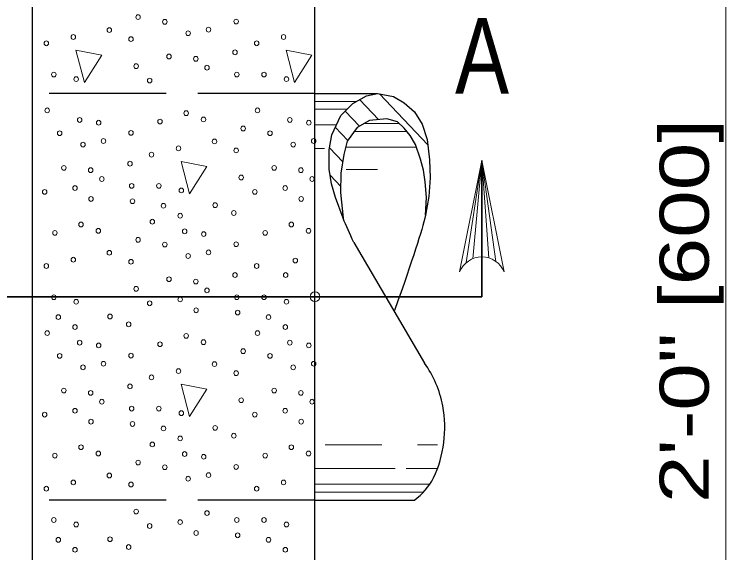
# Model space of a CAD drawing. Extents: x -410.5 to -376.5, y 1617.6 to 1661.6.
# Drawn here: x -401.689 to -399.43, y 1623.076 to 1624.784 of the extents above; entities that cross this region are included whole.
import ezdxf
from ezdxf.enums import TextEntityAlignment as Align

# ---------------------------------------------------------------- set-up
doc = ezdxf.new("R2010")
doc.units = 0
doc.header["$LTSCALE"] = 0.062
doc.header["$PDMODE"] = 32
doc.header["$PDSIZE"] = 0.031
doc.linetypes.add('LONG_DASHED', pattern=[7.5, 6, -1.5])
doc.layers.add('1', color=7, linetype='Continuous', lineweight=13)

msp = doc.modelspace()

# ---------------------------------------------------------------- linework, layer by layer
at = {"layer": '1'}
for p, q in [((-399.42975, 1626.3615), (-399.42975, 1621.41433)), ((-400.82575, 1624.67075), (-400.79875, 1624.56825)), ((-400.529, 1624.53167), (-400.376, 1624.36975)), ((-400.73433, 1624.508), (-400.60125, 1624.508)), ((-400.59167, 1624.51333), (-400.53217, 1624.45025)), ((-400.73433, 1624.483), (-400.63208, 1624.483)), ((-400.63783, 1624.47725), (-400.59275, 1624.4295)), ((-400.73433, 1624.433), (-400.66625, 1624.433)), ((-400.57825, 1624.43783), (-400.46692, 1624.43783)), ((-400.6695, 1624.426), (-400.62967, 1624.38392)), ((-400.60917, 1624.41283), (-400.4425, 1624.41283)), ((-400.63642, 1624.36292), (-400.412, 1624.36292)), ((-400.73433, 1624.35808), (-400.704, 1624.35808)), ((-400.68775, 1624.36058), (-400.64608, 1624.31642)), ((-400.25383, 1623.99633), (-400.20425, 1624.32058)), ((-400.233, 1624.00858), (-400.20425, 1624.32058)), ((-400.20425, 1624.01425), (-400.20425, 1624.32058)), ((-400.18158, 1624.011), (-400.20425, 1624.32058)), ((-400.15942, 1624.00008), (-400.20425, 1624.32058)), ((-400.68583, 1624.27375), (-400.65225, 1624.23825)), ((-400.63492, 1624.29208), (-400.536, 1624.29208)), ((-400.65, 1624.151), (-400.64575, 1624.14642)), ((-400.64617, 1624.14033), (-400.645, 1624.13925)), ((-400.70208, 1623.41775), (-400.52225, 1623.41775)), ((-400.409, 1623.41775), (-400.34525, 1623.41775)), ((-400.73433, 1623.34283), (-400.47942, 1623.34283)), ((-400.44417, 1623.34283), (-400.34525, 1623.34283)), ((-400.73433, 1623.29283), (-400.37, 1623.29283)), ((-400.73433, 1623.26783), (-400.39025, 1623.26783))]:
    msp.add_line(p, q, dxfattribs=at)
at = {"layer": '1', "linetype": 'LONG_DASHED', "lineweight": 25}
for p, q in [((-400.73433, 1624.533), (-401.63108, 1624.533)), ((-400.73433, 1623.24292), (-401.63108, 1623.24292))]:
    msp.add_line(p, q, dxfattribs=at)
at = {"layer": '1', "lineweight": 25}
for p, q in [((-400.73433, 1624.533), (-400.5355, 1624.533)), ((-400.61067, 1624.0605), (-400.38658, 1623.67742)), ((-400.73433, 1623.24292), (-400.41833, 1623.24292))]:
    msp.add_line(p, q, dxfattribs=at)
at = {"layer": '1', "lineweight": 35}
for p, q in [((-400.20425, 1623.88792), (-400.20425, 1624.32058)), ((-402.17842, 1623.88792), (-400.20425, 1623.88792))]:
    msp.add_line(p, q, dxfattribs=at)
at = {"layer": '1', "lineweight": 25}
for points in [[(-405.35992, 1621.41425), (-400.73433, 1621.41425), (-400.73433, 1626.3615), (-405.35992, 1626.3615)], [(-404.46308, 1625.41208), (-404.46308, 1622.36375), (-401.63108, 1622.36375), (-401.63108, 1625.41208)]]:
    msp.add_lwpolyline(points, close=True, dxfattribs=at)
at = {"layer": '1'}
for points in [[(-401.49325, 1624.67075), (-401.46625, 1624.56825), (-401.41125, 1624.65475)], [(-401.15942, 1624.31733), (-401.13242, 1624.21492), (-401.0775, 1624.30133)], [(-401.15942, 1623.61067), (-401.13242, 1623.50825), (-401.0775, 1623.59467)]]:
    msp.add_lwpolyline(points, close=True, dxfattribs=at)
for points in [[(-400.79875, 1624.56825), (-400.74375, 1624.65475), (-400.82575, 1624.67075)], [(-400.38283, 1624.14692), (-400.37975, 1624.20275), (-400.38442, 1624.25233), (-400.38992, 1624.29017), (-400.39908, 1624.32425), (-400.41467, 1624.37092), (-400.43217, 1624.39917), (-400.4505, 1624.42342), (-400.47258, 1624.44283), (-400.50567, 1624.45258), (-400.56067, 1624.44775), (-400.60025, 1624.42533), (-400.63142, 1624.38167), (-400.6425, 1624.33983), (-400.65167, 1624.2805), (-400.65258, 1624.21925), (-400.64483, 1624.13683)], [(-400.275, 1623.96658), (-400.20425, 1624.32058), (-400.13342, 1623.96658)]]:
    msp.add_lwpolyline(points, dxfattribs=at)
at = {"layer": '1', "lineweight": 25}
for points in [[(-400.64483, 1624.13683), (-400.66917, 1624.203), (-400.68133, 1624.24617), (-400.689, 1624.29233), (-400.68875, 1624.35433), (-400.68092, 1624.4015), (-400.6525, 1624.46275), (-400.61383, 1624.501), (-400.57067, 1624.52508), (-400.5355, 1624.533), (-400.48517, 1624.52333), (-400.4505, 1624.50292), (-400.41842, 1624.475), (-400.39408, 1624.43583), (-400.378, 1624.3865), (-400.37, 1624.32242), (-400.36833, 1624.265), (-400.37208, 1624.20617), (-400.38283, 1624.14692)], [(-400.64483, 1624.13683), (-400.66917, 1624.203), (-400.68133, 1624.24617), (-400.689, 1624.29233), (-400.68875, 1624.35433), (-400.68092, 1624.4015), (-400.6525, 1624.46275), (-400.61383, 1624.501), (-400.57067, 1624.52508), (-400.5355, 1624.533), (-400.48517, 1624.52333), (-400.4505, 1624.50292), (-400.41842, 1624.475), (-400.39408, 1624.43583), (-400.378, 1624.3865), (-400.37, 1624.32242), (-400.36833, 1624.265), (-400.37208, 1624.20617), (-400.38283, 1624.14692)], [(-400.38283, 1624.14692), (-400.37975, 1624.20275), (-400.38442, 1624.25233), (-400.38992, 1624.29017), (-400.39908, 1624.32425), (-400.41467, 1624.37092), (-400.43217, 1624.39917), (-400.4505, 1624.42342), (-400.47258, 1624.44283), (-400.50567, 1624.45258), (-400.56067, 1624.44775), (-400.60025, 1624.42533), (-400.63142, 1624.38167), (-400.6425, 1624.33983), (-400.65167, 1624.2805), (-400.65258, 1624.21925), (-400.64483, 1624.13683)]]:
    msp.add_lwpolyline(points, dxfattribs=at)
at = {"layer": '1'}
msp.add_arc((-400.20416, 1623.938), 0.0764, 22.08782, 157.91395, dxfattribs=at)
for centre, major_axis in [((-401.29579, 1624.77528), (0, 0.00756)), ((-400.98457, 1624.76121), (0, -0.00756)), ((-401.2108, 1624.76032), (0, 0.00756)), ((-401.38685, 1624.73423), (0, 0.00756)), ((-401.13693, 1624.72404), (0, -0.00756)), ((-401.07201, 1624.73553), (0, -0.00756)), ((-401.50127, 1624.71227), (0, -0.00756)), ((-401.31832, 1624.70561), (0, 0.00756)), ((-400.83377, 1624.71227), (0, -0.00756)), ((-401.58694, 1624.69224), (0, -0.00756)), ((-400.91943, 1624.69224), (0, -0.00756)), ((-401.19756, 1624.65031), (0, -0.00756)), ((-400.98785, 1624.66362), (0, -0.00756)), ((-401.11251, 1624.64295), (0, -0.00756)), ((-401.30208, 1624.61975), (0, -0.00756)), ((-401.07707, 1624.61498), (0, -0.00756)), ((-401.56341, 1624.59301), (0, 0.00756)), ((-400.98245, 1624.59301), (0, -0.00756)), ((-400.8959, 1624.59301), (0, 0.00756)), ((-401.49226, 1624.5787), (0, -0.00756)), ((-401.2588, 1624.57393), (0, -0.00756)), ((-400.82476, 1624.5787), (0, -0.00756)), ((-401.58421, 1624.47947), (0, 0.00756)), ((-401.14316, 1624.47058), (0, -0.00756)), ((-400.9167, 1624.47947), (0, 0.00756)), ((-401.48142, 1624.44896), (0, 0.00756)), ((-401.0882, 1624.45055), (0, -0.00756)), ((-400.81391, 1624.44896), (0, 0.00756)), ((-401.42106, 1624.4403), (0, -0.00756)), ((-401.22609, 1624.4439), (0, -0.00756)), ((-400.75355, 1624.4403), (0, -0.00756)), ((-401.54455, 1624.40697), (0, 0.00756)), ((-401.31832, 1624.40786), (0, -0.00756)), ((-400.96204, 1624.42193), (0, 0.00756)), ((-400.87704, 1624.40697), (0, 0.00756)), ((-401.40577, 1624.38218), (0, -0.00756)), ((-401.0531, 1624.38088), (0, 0.00756)), ((-400.73826, 1624.38218), (0, -0.00756)), ((-401.47068, 1624.37069), (0, -0.00756)), ((-401.16752, 1624.35892), (0, -0.00756)), ((-400.80317, 1624.37069), (0, -0.00756)), ((-401.25318, 1624.33889), (0, -0.00756)), ((-400.98457, 1624.35226), (0, 0.00756)), ((-401.3216, 1624.31027), (0, -0.00756)), ((-401.53131, 1624.29696), (0, -0.00756)), ((-401.44626, 1624.2896), (0, -0.00756)), ((-400.8638, 1624.29696), (0, -0.00756)), ((-400.77875, 1624.2896), (0, -0.00756)), ((-400.96833, 1624.2664), (0, -0.00756)), ((-401.41083, 1624.26163), (0, -0.00756)), ((-400.74332, 1624.26163), (0, -0.00756)), ((-401.59256, 1624.22058), (0, -0.00756)), ((-401.49616, 1624.23301), (0, -0.00756)), ((-401.31621, 1624.23966), (0, -0.00756)), ((-401.22965, 1624.23966), (0, 0.00756)), ((-401.15851, 1624.22535), (0, -0.00756)), ((-400.92505, 1624.22058), (0, -0.00756)), ((-400.82865, 1624.23301), (0, -0.00756)), ((-401.44537, 1624.19832), (0, -0.00756)), ((-400.77786, 1624.19832), (0, -0.00756)), ((-401.31354, 1624.19102), (0, -0.00756)), ((-401.21525, 1624.17671), (0, 0.00756)), ((-401.05126, 1624.17859), (0, -0.00756)), ((-400.9918, 1624.1538), (0, -0.00756)), ((-401.16213, 1624.1452), (0, 0.00756)), ((-401.47691, 1624.11723), (0, -0.00756)), ((-401.25046, 1624.12612), (0, 0.00756)), ((-400.8094, 1624.11723), (0, -0.00756)), ((-401.55985, 1624.09055), (0, -0.00756)), ((-401.42195, 1624.0972), (0, -0.00756)), ((-401.14766, 1624.09561), (0, 0.00756)), ((-401.08731, 1624.08695), (0, -0.00756)), ((-400.89234, 1624.09055), (0, -0.00756)), ((-400.75444, 1624.0972), (0, -0.00756)), ((-401.29579, 1624.06858), (0, 0.00756)), ((-401.2108, 1624.05362), (0, 0.00756)), ((-400.98457, 1624.05451), (0, -0.00756)), ((-401.38685, 1624.02753), (0, 0.00756)), ((-401.13693, 1624.01734), (0, -0.00756)), ((-401.07201, 1624.02883), (0, -0.00756)), ((-401.50127, 1624.00557), (0, -0.00756)), ((-401.31832, 1623.99891), (0, 0.00756)), ((-400.7966, 1624.00289), (0, -0.00756)), ((-401.58694, 1623.98554), (0, -0.00756)), ((-400.91943, 1623.98554), (0, -0.00756)), ((-400.98785, 1623.95692), (0, -0.00756)), ((-400.8272, 1623.95692), (0, -0.00756)), ((-401.19756, 1623.94361), (0, -0.00756)), ((-401.11251, 1623.93625), (0, -0.00756)), ((-401.30208, 1623.91305), (0, -0.00756)), ((-401.07707, 1623.90828), (0, -0.00756)), ((-401.56341, 1623.88631), (0, 0.00756)), ((-400.98245, 1623.88631), (0, -0.00756)), ((-400.8959, 1623.88631), (0, 0.00756)), ((-401.49226, 1623.872), (0, -0.00756)), ((-401.2588, 1623.86723), (0, -0.00756)), ((-401.1624, 1623.87966), (0, -0.00756)), ((-400.82476, 1623.872), (0, -0.00756)), ((-401.11162, 1623.84497), (0, -0.00756)), ((-400.97978, 1623.83767), (0, -0.00756)), ((-401.549, 1623.82336), (0, 0.00756)), ((-401.38502, 1623.82524), (0, -0.00756)), ((-400.88149, 1623.82336), (0, 0.00756)), ((-401.49588, 1623.79185), (0, 0.00756)), ((-401.32555, 1623.80045), (0, -0.00756)), ((-400.82837, 1623.79185), (0, 0.00756)), ((-401.58421, 1623.77277), (0, 0.00756)), ((-400.9167, 1623.77277), (0, 0.00756)), ((-401.14316, 1623.76388), (0, -0.00756)), ((-401.48142, 1623.74226), (0, 0.00756)), ((-401.42106, 1623.73361), (0, -0.00756)), ((-401.22609, 1623.7372), (0, -0.00756)), ((-401.0882, 1623.74385), (0, -0.00756)), ((-400.81391, 1623.74226), (0, 0.00756)), ((-400.75355, 1623.73361), (0, -0.00756)), ((-401.54455, 1623.70027), (0, 0.00756)), ((-401.31832, 1623.70116), (0, -0.00756)), ((-400.96204, 1623.71523), (0, 0.00756)), ((-400.87704, 1623.70027), (0, 0.00756)), ((-401.47068, 1623.664), (0, -0.00756)), ((-401.40577, 1623.67548), (0, -0.00756)), ((-401.0531, 1623.67418), (0, 0.00756)), ((-400.80317, 1623.664), (0, -0.00756)), ((-400.73826, 1623.67548), (0, -0.00756)), ((-401.25318, 1623.63219), (0, -0.00756)), ((-401.16752, 1623.65222), (0, -0.00756)), ((-400.98457, 1623.64556), (0, 0.00756)), ((-401.53131, 1623.59026), (0, -0.00756)), ((-401.3216, 1623.60357), (0, -0.00756)), ((-400.8638, 1623.59026), (0, -0.00756)), ((-401.44626, 1623.5829), (0, -0.00756)), ((-400.77875, 1623.5829), (0, -0.00756)), ((-401.41083, 1623.55493), (0, -0.00756)), ((-400.96833, 1623.5597), (0, -0.00756)), ((-400.74332, 1623.55493), (0, -0.00756)), ((-401.49616, 1623.52631), (0, -0.00756)), ((-401.31621, 1623.53296), (0, -0.00756)), ((-401.22965, 1623.53296), (0, 0.00756)), ((-401.15851, 1623.51865), (0, -0.00756)), ((-400.82865, 1623.52631), (0, -0.00756)), ((-401.59256, 1623.51388), (0, -0.00756)), ((-400.92505, 1623.51388), (0, -0.00756)), ((-401.44537, 1623.49162), (0, -0.00756)), ((-401.31354, 1623.48432), (0, -0.00756)), ((-400.77786, 1623.49162), (0, -0.00756)), ((-401.21525, 1623.47001), (0, 0.00756)), ((-401.05126, 1623.47189), (0, -0.00756)), ((-401.16213, 1623.4385), (0, 0.00756)), ((-400.9918, 1623.4471), (0, -0.00756)), ((-401.47691, 1623.41053), (0, -0.00756)), ((-401.25046, 1623.41942), (0, 0.00756)), ((-400.8094, 1623.41053), (0, -0.00756)), ((-401.55985, 1623.38385), (0, -0.00756)), ((-401.42195, 1623.3905), (0, -0.00756)), ((-401.14766, 1623.38891), (0, 0.00756)), ((-400.89234, 1623.38385), (0, -0.00756)), ((-400.75444, 1623.3905), (0, -0.00756)), ((-401.29579, 1623.36188), (0, 0.00756)), ((-401.08731, 1623.38026), (0, -0.00756)), ((-401.2108, 1623.34692), (0, 0.00756)), ((-400.98457, 1623.34781), (0, -0.00756)), ((-401.38685, 1623.32083), (0, 0.00756)), ((-401.07201, 1623.32213), (0, -0.00756)), ((-401.50127, 1623.29887), (0, -0.00756)), ((-401.13693, 1623.31065), (0, -0.00756)), ((-400.83377, 1623.29887), (0, -0.00756)), ((-401.58694, 1623.27884), (0, -0.00756)), ((-401.31832, 1623.29221), (0, 0.00756)), ((-400.91943, 1623.27884), (0, -0.00756)), ((-401.30208, 1623.20635), (0, -0.00756)), ((-401.56341, 1623.17961), (0, 0.00756)), ((-401.07707, 1623.20158), (0, -0.00756)), ((-400.98245, 1623.17961), (0, -0.00756)), ((-400.8959, 1623.17961), (0, 0.00756)), ((-401.49226, 1623.1653), (0, -0.00756)), ((-401.2588, 1623.16053), (0, -0.00756)), ((-401.1624, 1623.17296), (0, -0.00756)), ((-400.82476, 1623.1653), (0, -0.00756)), ((-401.11162, 1623.13827), (0, -0.00756)), ((-401.549, 1623.11666), (0, 0.00756)), ((-401.38502, 1623.11854), (0, -0.00756)), ((-400.97978, 1623.13097), (0, -0.00756)), ((-400.88149, 1623.11666), (0, 0.00756)), ((-401.32555, 1623.09375), (0, -0.00756)), ((-401.49588, 1623.08515), (0, 0.00756)), ((-400.82837, 1623.08515), (0, 0.00756))]:
    msp.add_ellipse(centre, major_axis=major_axis, ratio=0.944543, dxfattribs=at)
at = {"layer": '1', "lineweight": 25}
for centre, major_axis, start_param, end_param in [((-400.62961, 1623.47864), (0, 0.3251), 4.9073919, 5.370128), ((-400.662, 1623.47303), (0, 0.35983), 4.2528342, 4.9042115), ((-400.53553, 1623.421), (0, -0.21709), 0.608535, 1.0523476)]:
    msp.add_ellipse(centre, major_axis=major_axis, ratio=0.944543, start_param=start_param, end_param=end_param, dxfattribs=at)
for points in [[(-400.61067, 1624.0605), (-400.62408, 1624.08867), (-400.63533, 1624.11408), (-400.64483, 1624.13683)], [(-400.38283, 1624.14692), (-400.39542, 1624.09542), (-400.42183, 1624.01267), (-400.48167, 1623.8445)]]:
    msp.add_open_spline(points, degree=3, dxfattribs=at)
at = {"layer": '1'}
msp.add_point((-400.73433, 1623.88792), dxfattribs=at)

# ---------------------------------------------------------------- texts
at = {"layer": '1', "width": 0.8}
msp.add_text('A', height=0.24, dxfattribs=at).set_placement((-400.20358, 1624.53258), align=Align.CENTER)
at = {"layer": '1', "width": 1.3}
msp.add_text('2\'-0" [600]', height=0.156, rotation=90, dxfattribs=at).set_placement((-399.48358, 1623.2335))

doc.saveas('drawing.dxf')
